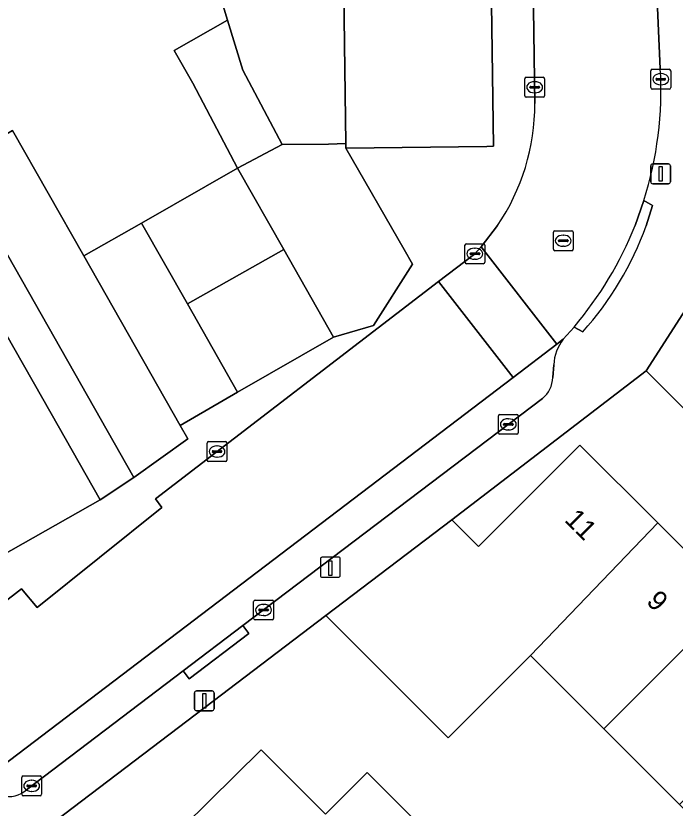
# Model space of a CAD drawing. Extents: x 159960 to 160866, y 382700 to 383354.
# Drawn here: x 160129.72 to 160162.95, y 383220.66 to 383260.57 of the extents above; entities that cross this region are included whole.
import ezdxf

# ---------------------------------------------------------------- set-up
doc = ezdxf.new("R2010")
doc.units = 0
for name, color, linetype in [('IMGEO_Erf', 7, 'Continuous'), ('IMGEO_Kolk', 7, 'Continuous'), ('IMGEO_Laadpaal', 7, 'Continuous'), ('IMGEO_Lichtmast', 7, 'Continuous'), ('IMGEO_Muur', 7, 'Continuous'), ('IMGEO_Pand', 7, 'Continuous'), ('IMGEO_Pand_nummerreeks', 7, 'Continuous'), ('IMGEO_Parkeervlak_open', 7, 'Continuous'), ('IMGEO_Rijbaan_lokaal_open', 7, 'Continuous'), ('IMGEO_Rioolput', 7, 'Continuous'), ('IMGEO_Voetpad_open', 7, 'Continuous')]:
    doc.layers.add(name, color=color, linetype=linetype)

msp = doc.modelspace()

# ---------------------------------------------------------------- linework, layer by layer
at = {"layer": 'IMGEO_Erf'}
for points in [[(160114.489, 383261.809), (160115.222, 383260.517), (160115.762, 383259.564), (160116.752, 383257.817), (160120.475, 383259.928), (160126.102, 383250), (160129.198, 383244.593), (160131.506, 383240.532), (160133.977, 383236.185), (160135.659, 383237.322), (160126.665, 383253.145), (160122.607, 383260.283), (160124.913, 383261.594), (160128.971, 383254.455), (160129.558, 383254.789), (160133.145, 383248.48), (160136.049, 383250.131), (160140.9, 383252.888), (160138.634, 383257.173), (160137.697, 383258.821), (160140.391, 383260.352), (160139.712, 383262.582)], [(160167.442, 383216.579), (160177.527, 383226.652), (160161.49, 383242.691), (160151.695, 383235.186), (160153.046, 383233.836), (160158.154, 383238.951), (160162.085, 383235.026), (160165.906, 383231.211), (160169.727, 383227.396), (160173.657, 383223.471), (160167.11, 383216.914), (160163.179, 383220.839), (160159.358, 383224.654), (160155.656, 383228.351), (160155.032, 383227.726), (160151.51, 383224.199), (160145.341, 383230.36), (160139.659, 383226.049), (160069.776, 383173.027)], [(160126.708, 383208.243), (160130.522, 383212.066), (160134.328, 383215.881), (160138.15, 383219.711), (160142.082, 383223.597), (160145.336, 383220.349), (160147.431, 383222.449), (160150.688, 383219.2), (160148.589, 383217.086), (160149.794, 383215.877), (160151.074, 383214.576), (160147.19, 383210.686), (160146.631, 383211.244), (160142.817, 383207.423), (160140.896, 383209.337), (160137.092, 383205.505), (160133.287, 383201.673), (160129.483, 383197.841)]]:
    msp.add_lwpolyline(points, dxfattribs=at)
msp.add_lwpolyline([(160146.349, 383253.911), (160146.346, 383254.139), (160145.473, 383254.11), (160143.151, 383254.083), (160140.9, 383252.888), (160143.222, 383248.803), (160145.738, 383244.377), (160147.755, 383244.967), (160149.722, 383248.052), (160149.29, 383248.802)], close=True, dxfattribs=at)
at = {"layer": 'IMGEO_Kolk'}
for p, q in [((160161.728, 383256.951), (160161.728, 383257.803)), ((160161.803, 383257.877), (160162.655, 383257.877)), ((160162.729, 383257.803), (160162.729, 383256.951)), ((160155.37, 383256.547), (160155.37, 383257.399)), ((160155.445, 383257.473), (160156.297, 383257.473)), ((160156.371, 383257.399), (160156.371, 383256.547)), ((160161.987, 383257.371), (160161.987, 383257.383)), ((160162.425, 383257.334), (160162.027, 383257.334)), ((160162.03, 383257.42), (160162.428, 383257.42)), ((160162.216, 383257.657), (160162.241, 383257.657)), ((160162.471, 383257.383), (160162.471, 383257.371)), ((160155.629, 383256.967), (160155.629, 383256.979)), ((160156.067, 383256.93), (160155.669, 383256.93)), ((160155.672, 383257.016), (160156.07, 383257.016)), ((160155.858, 383257.253), (160155.883, 383257.253)), ((160156.113, 383256.979), (160156.113, 383256.967)), ((160162.655, 383256.877), (160161.803, 383256.877)), ((160162.239, 383257.097), (160162.214, 383257.097)), ((160155.881, 383256.693), (160155.856, 383256.693)), ((160156.297, 383256.473), (160155.445, 383256.473)), ((160152.357, 383248.159), (160152.357, 383249.011)), ((160152.432, 383249.085), (160153.284, 383249.085)), ((160153.358, 383249.011), (160153.358, 383248.159)), ((160152.616, 383248.579), (160152.616, 383248.591)), ((160153.054, 383248.542), (160152.656, 383248.542)), ((160152.659, 383248.628), (160153.057, 383248.628)), ((160152.845, 383248.865), (160152.87, 383248.865)), ((160153.1, 383248.591), (160153.1, 383248.579)), ((160152.868, 383248.305), (160152.843, 383248.305)), ((160153.284, 383248.085), (160152.432, 383248.085)), ((160154.043, 383239.565), (160154.043, 383240.417)), ((160154.118, 383240.491), (160154.97, 383240.491)), ((160154.531, 383240.271), (160154.556, 383240.271)), ((160155.044, 383240.417), (160155.044, 383239.565)), ((160154.302, 383239.985), (160154.302, 383239.997)), ((160154.74, 383239.948), (160154.342, 383239.948)), ((160154.345, 383240.034), (160154.743, 383240.034)), ((160154.786, 383239.997), (160154.786, 383239.985)), ((160154.97, 383239.491), (160154.118, 383239.491)), ((160154.554, 383239.711), (160154.529, 383239.711)), ((160139.36, 383238.196), (160139.36, 383239.048)), ((160139.435, 383239.122), (160140.287, 383239.122)), ((160140.361, 383239.048), (160140.361, 383238.196)), ((160139.619, 383238.616), (160139.619, 383238.628)), ((160140.057, 383238.579), (160139.659, 383238.579)), ((160139.662, 383238.665), (160140.06, 383238.665)), ((160139.848, 383238.902), (160139.873, 383238.902)), ((160140.103, 383238.628), (160140.103, 383238.616)), ((160140.287, 383238.122), (160139.435, 383238.122)), ((160139.871, 383238.342), (160139.846, 383238.342)), ((160141.707, 383230.216), (160141.707, 383231.068)), ((160141.782, 383231.142), (160142.634, 383231.142)), ((160142.708, 383231.068), (160142.708, 383230.216)), ((160141.966, 383230.636), (160141.966, 383230.648)), ((160142.404, 383230.599), (160142.006, 383230.599)), ((160142.009, 383230.685), (160142.407, 383230.685)), ((160142.195, 383230.922), (160142.22, 383230.922)), ((160142.45, 383230.648), (160142.45, 383230.636)), ((160142.634, 383230.142), (160141.782, 383230.142)), ((160142.218, 383230.362), (160142.193, 383230.362)), ((160130.015, 383221.356), (160130.015, 383222.208)), ((160130.09, 383222.282), (160130.942, 383222.282)), ((160131.016, 383222.208), (160131.016, 383221.356)), ((160130.274, 383221.776), (160130.274, 383221.788)), ((160130.317, 383221.825), (160130.715, 383221.825)), ((160130.503, 383222.062), (160130.528, 383222.062)), ((160130.758, 383221.788), (160130.758, 383221.776)), ((160130.712, 383221.739), (160130.314, 383221.739)), ((160130.526, 383221.502), (160130.501, 383221.502)), ((160130.942, 383221.282), (160130.09, 383221.282))]:
    msp.add_line(p, q, dxfattribs=at)
for points in [[(160161.728, 383256.951), (160161.728, 383257.803)], [(160161.803, 383257.877), (160162.655, 383257.877)], [(160162.729, 383257.803), (160162.729, 383256.951)], [(160155.37, 383256.547), (160155.37, 383257.399)], [(160155.445, 383257.473), (160156.297, 383257.473)], [(160156.371, 383257.399), (160156.371, 383256.547)], [(160162.655, 383256.877), (160161.803, 383256.877)], [(160156.297, 383256.473), (160155.445, 383256.473)], [(160152.357, 383248.159), (160152.357, 383249.011)], [(160152.432, 383249.085), (160153.284, 383249.085)], [(160153.358, 383249.011), (160153.358, 383248.159)], [(160153.284, 383248.085), (160152.432, 383248.085)], [(160154.043, 383239.565), (160154.043, 383240.417)], [(160154.118, 383240.491), (160154.97, 383240.491)], [(160155.044, 383240.417), (160155.044, 383239.565)], [(160154.97, 383239.491), (160154.118, 383239.491)], [(160139.36, 383238.196), (160139.36, 383239.048)], [(160139.435, 383239.122), (160140.287, 383239.122)], [(160140.361, 383239.048), (160140.361, 383238.196)], [(160140.287, 383238.122), (160139.435, 383238.122)], [(160141.707, 383230.216), (160141.707, 383231.068)], [(160141.782, 383231.142), (160142.634, 383231.142)], [(160142.708, 383231.068), (160142.708, 383230.216)], [(160142.634, 383230.142), (160141.782, 383230.142)], [(160130.015, 383221.356), (160130.015, 383222.208)], [(160130.09, 383222.282), (160130.942, 383222.282)], [(160131.016, 383222.208), (160131.016, 383221.356)], [(160130.942, 383221.282), (160130.09, 383221.282)]]:
    msp.add_lwpolyline(points, dxfattribs=at)
for centre, radius, start, end in [((160161.805, 383257.801), 0.0765, 91.552, 178.448), ((160161.805, 383257.801), 0.0765, 91.552, 178.448), ((160162.653, 383257.801), 0.0765, 1.552, 88.448), ((160162.653, 383257.801), 0.0765, 1.552, 88.448), ((160155.447, 383257.397), 0.0765, 91.552, 178.448), ((160155.447, 383257.397), 0.0765, 91.552, 178.448), ((160156.295, 383257.397), 0.0765, 1.552, 88.448), ((160156.295, 383257.397), 0.0765, 1.552, 88.448), ((160162.027, 383257.38), 0.0403, 85.8775, 175.7526), ((160162.024, 383257.37), 0.0366, 178.938, 274.7102), ((160162.428, 383257.377), 0.043, 264.8664, 352.4533), ((160162.432, 383257.382), 0.0386, 1.7309, 96.639), ((160155.669, 383256.976), 0.0403, 85.8775, 175.7526), ((160155.666, 383256.966), 0.0366, 178.938, 274.7102), ((160156.07, 383256.973), 0.043, 264.8664, 352.4533), ((160156.074, 383256.978), 0.0386, 1.7309, 96.639), ((160161.805, 383256.953), 0.0765, 181.552, 268.448), ((160161.805, 383256.953), 0.0765, 181.552, 268.448), ((160162.653, 383256.953), 0.0765, 271.552, 358.448), ((160162.653, 383256.953), 0.0765, 271.552, 358.448), ((160155.447, 383256.549), 0.0765, 181.552, 268.448), ((160155.447, 383256.549), 0.0765, 181.552, 268.448), ((160156.295, 383256.549), 0.0765, 271.552, 358.448), ((160156.295, 383256.549), 0.0765, 271.552, 358.448), ((160152.434, 383249.009), 0.0765, 91.552, 178.448), ((160152.434, 383249.009), 0.0765, 91.552, 178.448), ((160153.282, 383249.009), 0.0765, 1.552, 88.448), ((160153.282, 383249.009), 0.0765, 1.552, 88.448), ((160152.656, 383248.588), 0.0403, 85.8775, 175.7526), ((160152.653, 383248.578), 0.0366, 178.938, 274.7102), ((160153.057, 383248.585), 0.043, 264.8664, 352.4533), ((160153.061, 383248.59), 0.0386, 1.7309, 96.639), ((160152.434, 383248.161), 0.0765, 181.552, 268.448), ((160152.434, 383248.161), 0.0765, 181.552, 268.448), ((160153.282, 383248.161), 0.0765, 271.552, 358.448), ((160153.282, 383248.161), 0.0765, 271.552, 358.448), ((160154.12, 383240.415), 0.0765, 91.552, 178.448), ((160154.12, 383240.415), 0.0765, 91.552, 178.448), ((160154.968, 383240.415), 0.0765, 1.552, 88.448), ((160154.968, 383240.415), 0.0765, 1.552, 88.448), ((160154.342, 383239.994), 0.0403, 85.8775, 175.7526), ((160154.339, 383239.984), 0.0366, 178.938, 274.7102), ((160154.743, 383239.991), 0.043, 264.8664, 352.4533), ((160154.747, 383239.996), 0.0386, 1.7309, 96.639), ((160154.12, 383239.567), 0.0765, 181.552, 268.448), ((160154.12, 383239.567), 0.0765, 181.552, 268.448), ((160154.968, 383239.567), 0.0765, 271.552, 358.448), ((160154.968, 383239.567), 0.0765, 271.552, 358.448), ((160139.437, 383239.046), 0.0765, 91.552, 178.448), ((160139.437, 383239.046), 0.0765, 91.552, 178.448), ((160140.285, 383239.046), 0.0765, 1.552, 88.448), ((160140.285, 383239.046), 0.0765, 1.552, 88.448), ((160139.659, 383238.625), 0.0403, 85.8775, 175.7526), ((160139.656, 383238.615), 0.0366, 178.938, 274.7102), ((160140.06, 383238.622), 0.043, 264.8664, 352.4533), ((160140.064, 383238.627), 0.0386, 1.7309, 96.639), ((160139.437, 383238.198), 0.0765, 181.552, 268.448), ((160139.437, 383238.198), 0.0765, 181.552, 268.448), ((160140.285, 383238.198), 0.0765, 271.552, 358.448), ((160140.285, 383238.198), 0.0765, 271.552, 358.448), ((160141.784, 383231.066), 0.0765, 91.552, 178.448), ((160141.784, 383231.066), 0.0765, 91.552, 178.448), ((160142.632, 383231.066), 0.0765, 1.552, 88.448), ((160142.632, 383231.066), 0.0765, 1.552, 88.448), ((160142.006, 383230.645), 0.0403, 85.8775, 175.7526), ((160142.003, 383230.635), 0.0366, 178.938, 274.7102), ((160142.407, 383230.642), 0.043, 264.8664, 352.4533), ((160142.411, 383230.647), 0.0386, 1.7309, 96.639), ((160141.784, 383230.218), 0.0765, 181.552, 268.448), ((160141.784, 383230.218), 0.0765, 181.552, 268.448), ((160142.632, 383230.218), 0.0765, 271.552, 358.448), ((160142.632, 383230.218), 0.0765, 271.552, 358.448), ((160130.092, 383222.206), 0.0765, 91.552, 178.448), ((160130.092, 383222.206), 0.0765, 91.552, 178.448), ((160130.94, 383222.206), 0.0765, 1.552, 88.448), ((160130.94, 383222.206), 0.0765, 1.552, 88.448), ((160130.314, 383221.785), 0.0403, 85.8775, 175.7526), ((160130.311, 383221.775), 0.0366, 178.938, 274.7102), ((160130.715, 383221.782), 0.043, 264.8664, 352.4533), ((160130.719, 383221.787), 0.0386, 1.7309, 96.639), ((160130.092, 383221.358), 0.0765, 181.552, 268.448), ((160130.092, 383221.358), 0.0765, 181.552, 268.448), ((160130.94, 383221.358), 0.0765, 271.552, 358.448), ((160130.94, 383221.358), 0.0765, 271.552, 358.448)]:
    msp.add_arc(centre, radius, start, end, dxfattribs=at)
for centre, major_axis, ratio, start_param, end_param in [((160162.215, 383257.377), (-0.387, 0.002), 0.722429, 4.712389, 7.853982), ((160162.24, 383257.377), (-0.39, 0.002), 0.717154, 1.570796, 4.712389), ((160155.857, 383256.973), (-0.387, 0.002), 0.722429, 4.712389, 7.853982), ((160155.882, 383256.973), (-0.39, 0.002), 0.717154, 1.570796, 4.712389), ((160152.844, 383248.585), (-0.387, 0.002), 0.722429, 4.712389, 7.853982), ((160152.869, 383248.585), (-0.39, 0.002), 0.717154, 1.570796, 4.712389), ((160154.53, 383239.991), (-0.387, 0.002), 0.722429, 4.712389, 7.853982), ((160154.555, 383239.991), (-0.39, 0.002), 0.717154, 1.570796, 4.712389), ((160139.847, 383238.622), (-0.387, 0.002), 0.722429, 4.712389, 7.853982), ((160139.872, 383238.622), (-0.39, 0.002), 0.717154, 1.570796, 4.712389), ((160142.194, 383230.642), (-0.387, 0.002), 0.722429, 4.712389, 7.853982), ((160142.219, 383230.642), (-0.39, 0.002), 0.717154, 1.570796, 4.712389), ((160130.502, 383221.782), (-0.387, 0.002), 0.722429, 4.712389, 7.853982), ((160130.527, 383221.782), (-0.39, 0.002), 0.717154, 1.570796, 4.712389)]:
    msp.add_ellipse(centre, major_axis=major_axis, ratio=ratio, start_param=start_param, end_param=end_param, dxfattribs=at)
at = {"layer": 'IMGEO_Laadpaal'}
for p, q in [((160145.074, 383233.214), (160145.074, 383232.373)), ((160145.074, 383233.214), (160145.074, 383232.373)), ((160145.99, 383233.298), (160145.149, 383233.298)), ((160145.99, 383233.298), (160145.149, 383233.298)), ((160146.074, 383232.382), (160146.074, 383233.223)), ((160146.074, 383232.382), (160146.074, 383233.223)), ((160145.158, 383232.298), (160145.999, 383232.298)), ((160145.158, 383232.298), (160145.999, 383232.298))]:
    msp.add_line(p, q, dxfattribs=at)
msp.add_lwpolyline([(160145.489, 383233.111), (160145.649, 383233.111), (160145.649, 383232.378), (160145.489, 383232.378), (160145.489, 383233.111)], dxfattribs=at)
for centre, start, end in [((160145.152, 383233.22), 92.4484, 184.2845), ((160145.152, 383233.22), 92.4484, 184.2845), ((160145.996, 383233.22), 2.4484, 94.2845), ((160145.996, 383233.22), 2.4484, 94.2845), ((160145.152, 383232.376), 182.4484, 274.2845), ((160145.152, 383232.376), 182.4484, 274.2845), ((160145.996, 383232.376), 272.4484, 4.2845), ((160145.996, 383232.376), 272.4484, 4.2845)]:
    msp.add_arc(centre, 0.0779, start, end, dxfattribs=at)
at = {"layer": 'IMGEO_Lichtmast'}
for p, q in [((160161.723, 383252.211), (160161.723, 383253.011)), ((160161.723, 383253.011), (160161.723, 383252.211)), ((160161.823, 383253.111), (160162.613, 383253.111)), ((160162.613, 383253.111), (160161.823, 383253.111)), ((160162.713, 383253.011), (160162.713, 383252.211)), ((160162.713, 383252.211), (160162.713, 383253.011)), ((160162.613, 383252.111), (160161.823, 383252.111)), ((160161.823, 383252.111), (160162.613, 383252.111)), ((160138.825, 383226.564), (160139.615, 383226.564)), ((160139.615, 383226.564), (160138.825, 383226.564)), ((160138.725, 383225.664), (160138.725, 383226.464)), ((160138.725, 383226.464), (160138.725, 383225.664)), ((160139.715, 383226.464), (160139.715, 383225.664)), ((160139.715, 383225.664), (160139.715, 383226.464)), ((160139.615, 383225.564), (160138.825, 383225.564)), ((160138.825, 383225.564), (160139.615, 383225.564))]:
    msp.add_line(p, q, dxfattribs=at)
for points in [[(160162.143, 383252.986), (160162.293, 383252.986), (160162.293, 383252.236), (160162.143, 383252.236), (160162.143, 383252.986)], [(160139.145, 383226.439), (160139.295, 383226.439), (160139.295, 383225.689), (160139.145, 383225.689), (160139.145, 383226.439)]]:
    msp.add_lwpolyline(points, dxfattribs=at)
for centre, start, end in [((160161.823, 383253.011), 90, 180), ((160161.823, 383253.011), 90, 180), ((160162.613, 383253.011), 0, 90), ((160162.613, 383253.011), 360, 90), ((160161.823, 383252.211), 180, 270), ((160161.823, 383252.211), 180, 270), ((160162.613, 383252.211), 270, 0), ((160162.613, 383252.211), 270, 0), ((160138.825, 383226.464), 90, 180), ((160138.825, 383226.464), 90, 180), ((160139.615, 383226.464), 0, 90), ((160139.615, 383226.464), 360, 90), ((160138.825, 383225.664), 180, 270), ((160138.825, 383225.664), 180, 270), ((160139.615, 383225.664), 270, 0), ((160139.615, 383225.664), 270, 0)]:
    msp.add_arc(centre, 0.1, start, end, dxfattribs=at)
at = {"layer": 'IMGEO_Muur'}
msp.add_lwpolyline([(160139.659, 383226.049), (160145.341, 383230.36)], dxfattribs=at)
at = {"layer": 'IMGEO_Pand'}
for points in [[(160153.481, 383276.747), (160153.377, 383284.295), (160146.117, 383284.164), (160145.534, 383284.157), (160145.656, 383273.765), (160145.964, 383273.767), (160145.997, 383270.772), (160145.673, 383270.75), (160146.176, 383267.1), (160146.182, 383266.849), (160146.233, 383263.133), (160146.288, 383259.139), (160146.346, 383254.139), (160146.349, 383253.911), (160153.457, 383253.993), (160153.79, 383253.997)], [(160146.288, 383259.139), (160146.233, 383263.133), (160139.539, 383263.067), (160139.712, 383262.582), (160140.391, 383260.352), (160141.158, 383257.837), (160143.151, 383254.083), (160145.473, 383254.11), (160146.346, 383254.139)], [(160129.558, 383254.789), (160128.971, 383254.455), (160124.913, 383261.594), (160122.607, 383260.283), (160126.665, 383253.145), (160135.659, 383237.322), (160138.389, 383239.256), (160138.008, 383239.926), (160133.145, 383248.48)], [(160126.102, 383250), (160120.475, 383259.928), (160116.752, 383257.817), (160115.762, 383259.564), (160115.222, 383260.517), (160112.892, 383259.198), (160112.35, 383258.891), (160117.54, 383250), (160120.35, 383245.187), (160128.149, 383231.828), (160128.24, 383231.897), (160127.825, 383232.712), (160133.977, 383236.185), (160131.506, 383240.532), (160129.198, 383244.593)], [(160140.391, 383260.352), (160137.697, 383258.821), (160138.634, 383257.173), (160140.9, 383252.888), (160143.151, 383254.083), (160141.158, 383257.837)], [(160140.9, 383252.888), (160136.049, 383250.131), (160138.364, 383246.058), (160143.222, 383248.803)], [(160138.364, 383246.058), (160136.049, 383250.131), (160133.145, 383248.48), (160138.008, 383239.926), (160140.887, 383241.619)], [(160138.364, 383246.058), (160140.887, 383241.619), (160145.738, 383244.377), (160143.222, 383248.803)], [(160162.085, 383235.026), (160158.154, 383238.951), (160153.046, 383233.836), (160151.695, 383235.186), (160145.341, 383230.36), (160151.51, 383224.199), (160155.032, 383227.726), (160155.656, 383228.351)], [(160165.906, 383231.211), (160162.085, 383235.026), (160155.656, 383228.351), (160159.358, 383224.654)], [(160165.906, 383231.211), (160159.358, 383224.654), (160163.179, 383220.839), (160169.727, 383227.396)], [(160150.688, 383219.2), (160147.431, 383222.449), (160145.336, 383220.349), (160142.082, 383223.597), (160138.15, 383219.711), (160144.702, 383213.17), (160146.631, 383211.244), (160147.19, 383210.686), (160151.074, 383214.576), (160149.794, 383215.877), (160148.589, 383217.086)]]:
    msp.add_lwpolyline(points, close=True, dxfattribs=at)
at = {"layer": 'IMGEO_Parkeervlak_open'}
for points in [[(160157.31, 383244.277), (160156.996, 383244.038), (160154.782, 383242.356), (160127, 383221.243)], [(160156.78, 383242.359), (160156.831, 383242.994)], [(160130.26, 383221.59), (160138.153, 383227.571), (160141.164, 383229.853), (160156.259, 383241.292)]]:
    msp.add_lwpolyline(points, dxfattribs=at)
for centre, radius, start, end in [((160159.112, 383242.873), 2.284, 142.0841, 176.9703), ((160155.397, 383242.373), 1.383, 308.5464, 359.4025), ((160129.401, 383222.503), 1.254, 252.1219, 313.2477)]:
    msp.add_arc(centre, radius, start, end, dxfattribs=at)
at = {"layer": 'IMGEO_Rijbaan_lokaal_open'}
for points in [[(160161.787, 383267.523), (160161.092, 383282.882), (160161.09, 383283.191), (160157.143, 383283.13), (160155.502, 383283.054), (160155.536, 383280.043), (160155.884, 383256.155)], [(160162.204, 383257.907), (160162.004, 383262.52), (160161.787, 383267.523)], [(160194.681, 383256.511), (160179.477, 383250), (160178.563, 383249.609), (160178.179, 383250), (160173.574, 383254.679), (160167.549, 383250), (160164.849, 383247.905), (160161.49, 383242.691), (160177.527, 383226.652)], [(160160.93, 383250), (160161.378, 383251.26)], [(160153.998, 383250), (160153.175, 383248.934), (160156.996, 383244.038), (160157.31, 383244.277), (160157.858, 383244.894)], [(160114.023, 383219.44), (160112.553, 383218.319), (160108.863, 383215.504), (160102.49, 383210.638), (160106.341, 383205.542), (160106.624, 383205.757), (160109.582, 383208.005), (160110.895, 383209.003), (160113.879, 383211.271), (160115.118, 383212.213), (160118.128, 383214.5), (160119.709, 383215.701), (160122.754, 383218.015), (160123.542, 383218.614), (160126.521, 383220.878), (160127, 383221.243), (160154.782, 383242.356), (160151.029, 383247.18), (160136.759, 383236.248), (160137.086, 383235.801), (160130.797, 383230.76), (160130.003, 383231.704), (160121.152, 383224.85)]]:
    msp.add_lwpolyline(points, dxfattribs=at)
msp.add_lwpolyline([(160153.175, 383248.934), (160152.842, 383248.569), (160151.029, 383247.18), (160154.782, 383242.356), (160156.996, 383244.038)], close=True, dxfattribs=at)
for centre, radius, start, end in [((160143.774, 383256.822), 18.462, 342.4649, 3.3678), ((160144.922, 383256.148), 10.962, 325.8895, 0.0385), ((160143.679, 383256.902), 18.58, 319.7394, 338.1945)]:
    msp.add_arc(centre, radius, start, end, dxfattribs=at)
at = {"layer": 'IMGEO_Rioolput'}
for p, q in [((160156.888, 383249.74), (160157.74, 383249.74)), ((160156.813, 383248.814), (160156.813, 383249.666)), ((160157.301, 383249.52), (160157.326, 383249.52)), ((160157.814, 383249.666), (160157.814, 383248.814)), ((160157.072, 383249.234), (160157.072, 383249.246)), ((160157.51, 383249.197), (160157.112, 383249.197)), ((160157.115, 383249.283), (160157.513, 383249.283)), ((160157.324, 383248.96), (160157.299, 383248.96)), ((160157.556, 383249.246), (160157.556, 383249.234)), ((160157.74, 383248.74), (160156.888, 383248.74))]:
    msp.add_line(p, q, dxfattribs=at)
for points in [[(160156.888, 383249.74), (160157.74, 383249.74)], [(160156.813, 383248.814), (160156.813, 383249.666)], [(160157.814, 383249.666), (160157.814, 383248.814)], [(160157.74, 383248.74), (160156.888, 383248.74)]]:
    msp.add_lwpolyline(points, dxfattribs=at)
for centre, radius, start, end in [((160156.89, 383249.664), 0.0765, 91.552, 178.448), ((160156.89, 383249.664), 0.0765, 91.552, 178.448), ((160157.738, 383249.664), 0.0765, 1.552, 88.448), ((160157.738, 383249.664), 0.0765, 1.552, 88.448), ((160157.112, 383249.243), 0.0403, 85.8775, 175.7526), ((160157.109, 383249.233), 0.0366, 178.938, 274.7102), ((160157.513, 383249.24), 0.043, 264.8664, 352.4533), ((160157.517, 383249.245), 0.0386, 1.7309, 96.639), ((160156.89, 383248.816), 0.0765, 181.552, 268.448), ((160156.89, 383248.816), 0.0765, 181.552, 268.448), ((160157.738, 383248.816), 0.0765, 271.552, 358.448), ((160157.738, 383248.816), 0.0765, 271.552, 358.448)]:
    msp.add_arc(centre, radius, start, end, dxfattribs=at)
for centre, major_axis, ratio, start_param, end_param in [((160157.3, 383249.24), (-0.387, 0.002), 0.722429, 4.712389, 7.853982), ((160157.325, 383249.24), (-0.39, 0.002), 0.717154, 1.570796, 4.712389)]:
    msp.add_ellipse(centre, major_axis=major_axis, ratio=ratio, start_param=start_param, end_param=end_param, dxfattribs=at)
at = {"layer": 'IMGEO_Voetpad_open'}
for points in [[(160139.659, 383226.049), (160145.341, 383230.36), (160151.695, 383235.186), (160161.49, 383242.691), (160164.849, 383247.905), (160164.765, 383250), (160164.266, 383262.534), (160164.075, 383268.216), (160163.482, 383280.605), (160163.378, 383283.205), (160163.306, 383284.974), (160161.045, 383284.911), (160161.09, 383283.191), (160161.092, 383282.882), (160161.787, 383267.523), (160162.286, 383267.544), (160162.503, 383262.541), (160162.004, 383262.52), (160162.204, 383257.907)], [(160155.884, 383256.155), (160155.536, 383280.043), (160155.502, 383283.054), (160155.469, 383284.131), (160153.377, 383284.295), (160153.481, 383276.747), (160153.79, 383253.997), (160153.457, 383253.993), (160146.349, 383253.911), (160149.29, 383248.802), (160149.722, 383248.052), (160147.755, 383244.967), (160145.738, 383244.377), (160140.887, 383241.619), (160138.008, 383239.926), (160138.389, 383239.256), (160135.659, 383237.322), (160133.977, 383236.185), (160127.825, 383232.712), (160128.24, 383231.897), (160128.149, 383231.828), (160120.387, 383225.893), (160119.597, 383225.284)], [(160161.488, 383249.995), (160161.816, 383251.018), (160161.378, 383251.26), (160160.93, 383250)], [(160161.378, 383251.26), (160161.816, 383251.018), (160161.488, 383249.995)], [(160137.086, 383235.801), (160136.759, 383236.248), (160151.029, 383247.18), (160152.842, 383248.569), (160153.175, 383248.934), (160153.998, 383250)], [(160158.295, 383244.653), (160157.858, 383244.894), (160157.31, 383244.277)], [(160157.858, 383244.894), (160158.295, 383244.653)], [(160156.831, 383242.994), (160156.78, 383242.359)], [(160156.259, 383241.292), (160141.164, 383229.853), (160141.468, 383229.457), (160138.457, 383227.175), (160138.153, 383227.571), (160130.26, 383221.59)], [(160121.152, 383224.85), (160130.003, 383231.704), (160130.797, 383230.76), (160137.086, 383235.801)], [(160069.776, 383173.027), (160139.659, 383226.049)]]:
    msp.add_lwpolyline(points, dxfattribs=at)
msp.add_lwpolyline([(160138.153, 383227.571), (160138.457, 383227.175), (160141.468, 383229.457), (160141.164, 383229.853)], close=True, dxfattribs=at)
for centre, radius, start, end in [((160143.774, 383256.822), 18.462, 342.4649, 3.3678), ((160144.922, 383256.148), 10.962, 325.8895, 0.0385), ((160143.679, 383256.902), 18.58, 319.7394, 338.1945), ((160146.374, 383255.403), 16.052, 317.955, 340.3102), ((160146.374, 383255.403), 16.052, 317.955, 340.3102), ((160159.112, 383242.873), 2.284, 142.0841, 176.9703), ((160155.397, 383242.373), 1.383, 308.5464, 359.4025), ((160129.401, 383222.503), 1.254, 252.1219, 313.2477)]:
    msp.add_arc(centre, radius, start, end, dxfattribs=at)

# ---------------------------------------------------------------- texts
at = {"layer": 'IMGEO_Pand_nummerreeks'}
for s, rotation, p in [('11', 315.04, (160157.334, 383235.135)), ('9', 315.0425, (160161.455, 383231.02))]:
    msp.add_text(s, height=1, rotation=rotation, dxfattribs=at).set_placement(p)

doc.saveas('drawing.dxf')
